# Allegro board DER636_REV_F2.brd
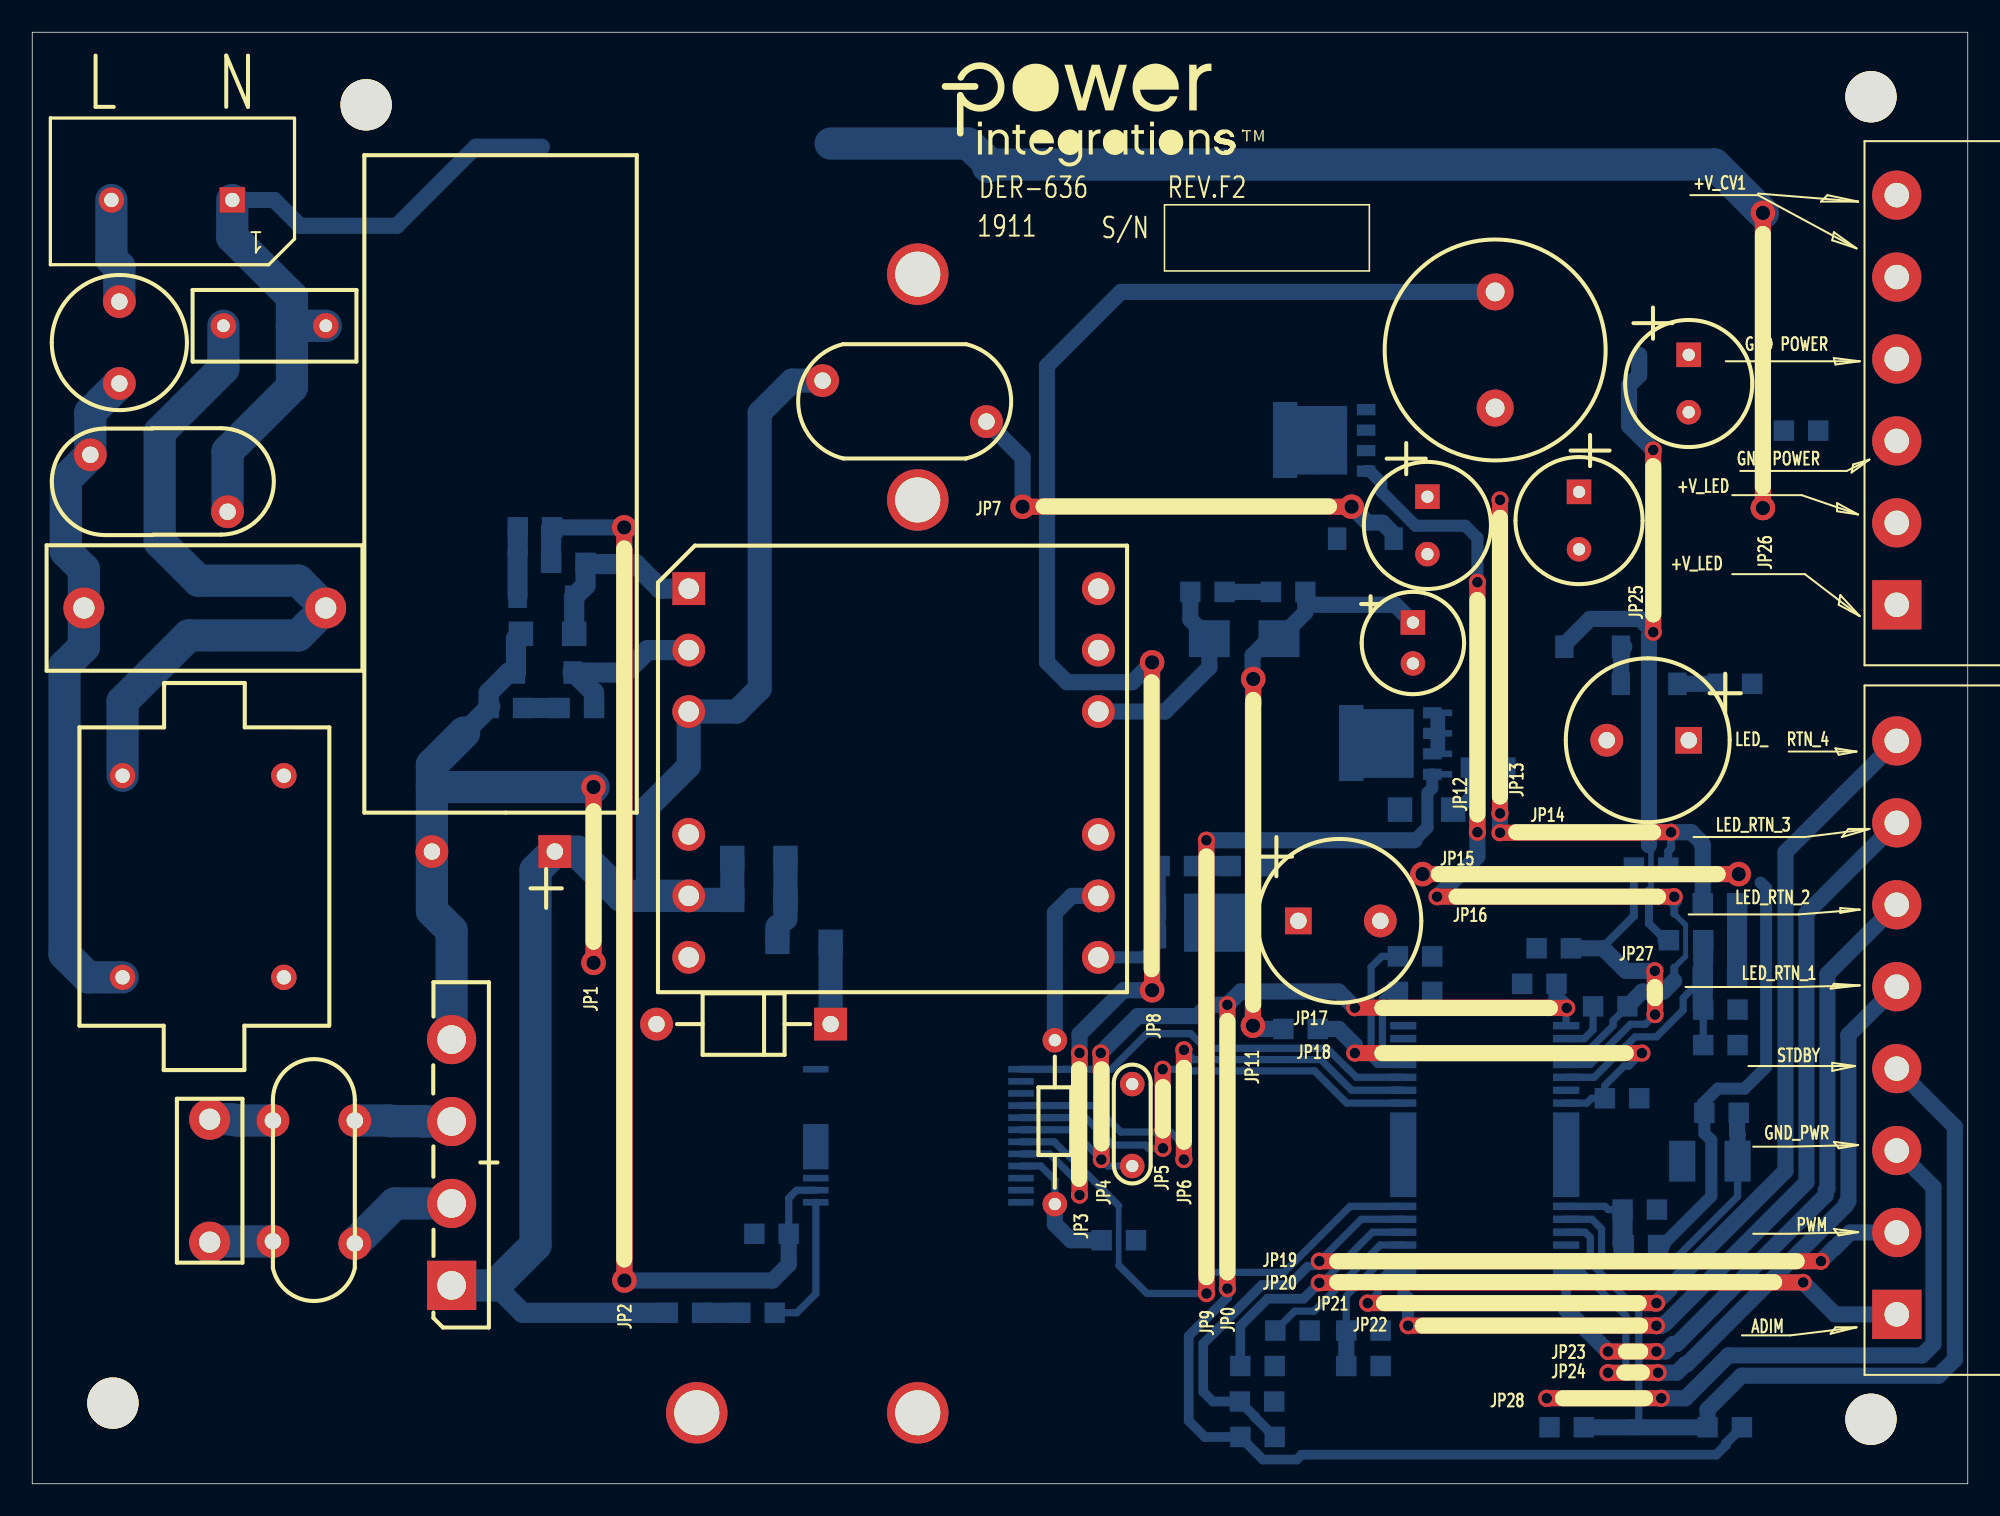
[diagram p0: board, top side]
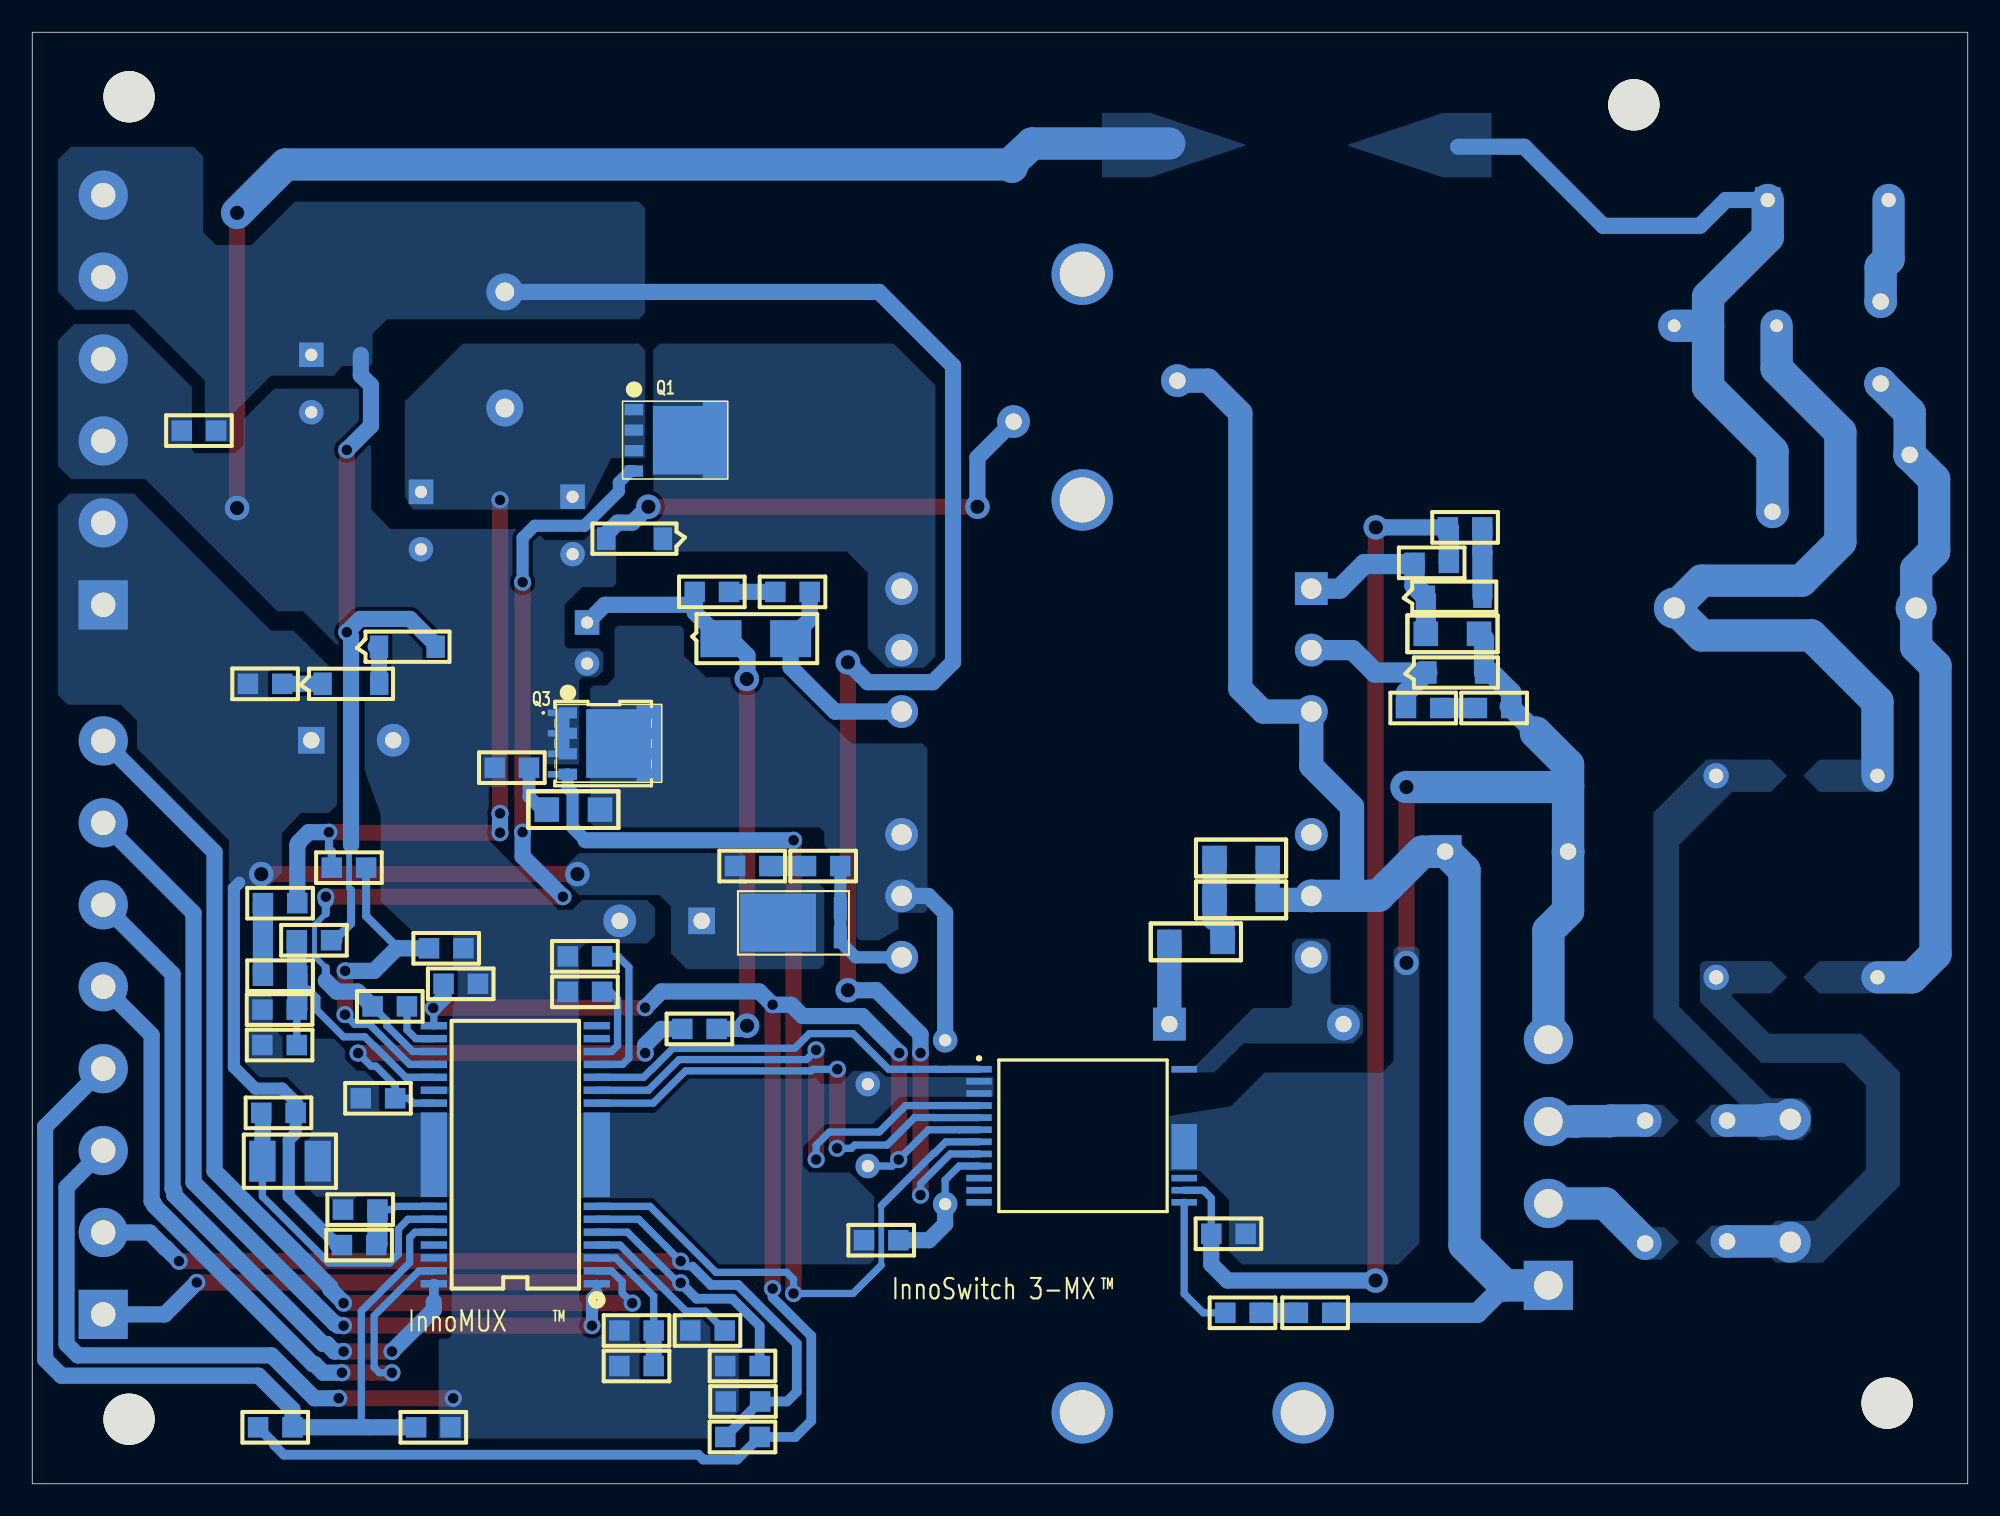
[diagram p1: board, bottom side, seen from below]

Outline 120 x 90 mm; copper layers: TOP, LAYER2, LAYER3, LAYER4, LAYER5, LAYER6, LAYER7, LAYER8, LAYER9, BOTTOM. Coordinates in mm from the lower left corner of the outline.
Outline path: 0,90 0,0 120,0 120,90 0,90

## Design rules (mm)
constraint set DEFAULT: min track width 0.1

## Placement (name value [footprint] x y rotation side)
BR1  GBU4J-BP  [PIDAXBRIDGEGBU8]  26 12.3 90 top
C1  33 nF  [PI_NP_CAP400X160LS300D040]  11 14.98 90 top
C2  220 nF  [PI_NP_710X315LS590D040]  3.2 54.3 0 top
C3  100 uF  [PIPOLCAPCLYD630LS300040]  32.4 39.2 180 top
C4  1000 uF  [PIPOLCAPCLYD320LS140030]  86.5 61.2 270 top
C5  1000  uF  [PIPOLCAPCLYD320LS140030]  102.7 70 270 top
C6  1 uF  [PISMC0805]  108.6 65.3 0 bottom
C7  1000 uF  [PIPOLCAPCLYD320LS140030]  95.9 61.5 270 top
C8  100 uF  [PIPOLCAPCYLD250LS100030]  85.6 53.4 270 top
C9  470 nF  [PISMC0805]  105.7 31.5 180 bottom
C10  100 pf  [PISMC0805]  76.8 55.3 0 bottom
C11  3.3 nF  [PINPYCAPRAD540X290LS400040]  49 68.4 0 top
C12  100 pf  [PISMC0805]  74.3 38.3 0 bottom
C13  1  nF  [PISMC1206]  43.4 38.8 0 bottom
C14  56 uF  [PIPOLCAPCYLD400LS200040]  78.5 34.9 0 top
C15  56 uF  [PIPOLCAPCYLD400LS200040]  102.7 46.1 180 top
C16  1 nF  [PISMC0805]  89.2 44.4 0 bottom
C17  100 nF  [PISMC0805]  95.4 33.2 180 bottom
C18  100 nF  [PISMC1210]  102.3 20 0 bottom
C19  100 nF  [PISMC0805]  97.5 23.9 0 bottom
C20  220 nF  [PISMC0805]  98.9 29.6 180 bottom
C21  100 nF  [PISMC0805]  79.2 9.5 180 bottom
C22  2.2 nF  [PISMC0805]  66.3 15.1 0 bottom
C23  2.2 uF  [PINPCAPRAD200X100200030]  68.2 19.7 90 top
C24  2.2 uF  [PISMC0805]  94.5 31 180 bottom
C28  100 pf  [PISMC0805]  28.3 48.1 0 bottom
C30  22 uF  [PISMC1206]  33.6 52.7 180 bottom
C31  4.7 uF  [PISMC0805]  46.9 15.5 180 bottom
CON2  TERMINAL BLOCK  [PI_TRMBLK_5P08_8PIN_H]  115.6 10.5 0 top
CON3  TERMINAL BLOCK  [PI_TRMBLK_5P08_6PIN_H]  115.6 54.5 0 top
D1  ES1C-13-F  [PISMDO214AC12]  77.3 52.4 180 bottom
D2  MMSZ5252BT1G  [PI_SM_SOD-123_12]  80.9 58.6 0 bottom
D3  PDU620-13  [PISMDPOWERDI5]  69.9 33.9 90 bottom
D4  BYV26C  [PIDV200X150X040SOD57]  49.5 28.5 180 top
D5  BAT46W-TP  [PI_SM_SOD-123_12]  33.5 50.3 180 bottom
D6  MMSZ5246B-7-F  [PI_SM_SOD-123_12]  33.6 55 180 bottom
F1  2 A  [PI_TR5_SUBMIN_FUSE]  5.4 73.3 270 top
J1  CON2  [PI_HDR_2PIN_PHOENIX_LS295]  12.4 79.6 180 top
L1  15 mH  [PIIND4P944X650LS492X394060]  15.6 43.9 270 top
L2  200 uH  [PI_COIL_2]  20 14.9 90 top
L3  10 uH  [PI_CHOKE_H625XD539LS290D046]  90.7 66.7 90 top
MTG_HOLE1  M 3  [PIMTGHOLEM3]  20.7 85.5 0 top
MTG_HOLE2  M 3  [PIMTGHOLEM3]  114 86 0 top
MTG_HOLE3  M 3  [PIMTGHOLEM3]  114 4 0 top
MTG_HOLE4  M 3  [PIMTGHOLEM3]  5 5 0 top
MTG_HOLE5  M 3  [PIMTGHOLEM3]  41.2 4.4 0 top
MTG_HOLE6  M 3  [PIMTGHOLEM3]  54.9 4.4 0 top
MTG_HOLE7  M 3  [PIMTGHOLEM3]  54.9 61 0 top
MTG_HOLE8  M 3  [PIMTGHOLEM3]  54.9 75 0 top
NOREF  -  []  120 0 90 top
NOREF#2  -  []  56.4 88.1 0 top
NOREF#3  -  []  0 90 0 top
Q1  SI4154DY-T1-GE3  [PI_SM_SOT669]  82.7 66.6 270 bottom
Q2  SQJA62EP-T1_GE3  [PISMPQFN5X6B]  87.4 47.8 270 bottom
Q3  SI4154DY-T1-GE3  [PI_SM_SOT669]  86.8 47.8 270 bottom
R1  10  [PIRAD400X175LS250031]  18.2 71.8 180 top
R2  10 k  [PISMR0805]  105.7 36 180 bottom
R3  10  [PISMR0805]  99.3 38.2 0 bottom
R4  10  [PISMR0805]  71.8 55.3 0 bottom
R5  10 k  [PISMR0805]  103.6 33.7 180 bottom
R6  100  [PISMR0805]  104.5 49.6 0 bottom
R7  390 k  [PISMR1206]  43.4 36.2 0 bottom
R8  10  [PISMR0805]  69.9 38.3 0 bottom
R9  10  [PISMR0805]  105.8 23 180 bottom
R10  10  [PISMR0805]  79.7 28.2 180 bottom
R11  121 k  [PISMR0805]  100.8 14.8 180 bottom
R12  3.30 k  [PISMR0805]  98.6 17 0 bottom
R13  10  [PISMR1206]  46.2 33.6 0 bottom
R14  18  [PISMR1206]  84.8 41.8 0 bottom
R15  68 k  [PISMR0805]  103.6 27.2 0 bottom
R16  3.30 k  [PISMR0805]  103.6 29.4 0 bottom
R17  47  [PI18WRESD080LS400D030]  63.4 27.5 270 top
R18  10 k  [PISMR0805]  83.6 9.5 180 bottom
R19  39 k  [PISMR0805]  86.8 30.5 180 bottom
R20  10  [PISMR0805]  32.7 48.1 0 bottom
R21  47.0  [PISMR0805]  30.1 59.3 0 bottom
R22  10 k  [PISMR0805]  34.3 57.1 180 bottom
R23  100 k  [PISMR0805]  74.9 7.3 0 bottom
R24  100 k  [PISMR0805]  96.2 3.5 180 bottom
R25  100 k  [PISMR0805]  77 5.1 180 bottom
R26  1.00 k  [PISMR0805]  106 3.5 180 bottom
R27  1.00 k  [PISMR0805]  74.9 2.9 0 bottom
R28  2 M  [PISMR0805]  39.4 10.6 0 bottom
R29  2 M  [PISMR0805]  43.9 10.6 0 bottom
R30  22 k  [PISMR0805]  86.8 32.7 180 bottom
R34  39 k  [PISMR0805]  83.6 7.3 180 bottom
T1  PQ26/20  [PI_BOBBIN_BPQ26_20_12P]  40.7 55.5 0 top
U1  MINNO (B)  [PI_SM_HSOP28_ALT]  85 12.4 90 bottom
U2  MINNO (A)  [PI_IC_INSOP_24D_IPC]  61.3 25.7 180 bottom
VDR1  275 Vac  [PIDISC500X225LS335X140040]  3.6 63.8 0 top
VR1  MMSZ5250B-7-F  [PI_SM_SOD-123_12]  98.5 51.9 180 bottom
VR2  MMSZ5245B-7-F  [PI_SM_SOD-123_12]  102 49.6 180 bottom

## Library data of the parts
BR1 = DISCRETE BRIDGE_+~~-
C1 C2 C6 C9 C10 C12 C13 C17-C24 C28 C30 C31 = CAP NP
C3 = CAP POL: alternate symbols: (pipolcapd630ls3000401600lhoriz)
C4 C7 = CAP POL
C5 = CAP POL: alternate symbols: (pipolcapclyd320ls140d30h750)
C8 = CAP POL: alternate symbols: (pipolcapcyld250ls100030h)
C11 = CAP NP: alternate symbols: (pinpycaprad540x290ls400040h)
C14 C15 = CAP POL: alternate symbols: (pipolcapcyld10ls514HD040H)
C16 = CAP NP: alternate symbols: (pismc0805_1)
CON2 = CON8
CON3 = CON6
D1 = DIODE
D2 D5 D6 VR1 VR2 = DIODE_ZENER
D3 = DIODE_PD5
D4 = DIODE: alternate symbols: (pidax425x150040sod57)
F1 = FUSE
J1 = CON2
L1 = INDUCTOR_4P_revD
L2 = TORRID 4P_14_23
L3 = INDUCTOR
MTG_HOLE1-MTG_HOLE8 = MTG_HOLE_M3
Q1 Q3 = FET_N_SGD_123_4_5: alternate symbols: (pismso8)
Q2 = FET_N_SGD_123_4_5678
R1 = THERMISTOR: alternate symbols: (pirad400x175ls250040_h)
R2-R16 R18-R30 R34 = R
R17 = R: alternate symbols: (pi18wresd080ls300d030,pi18wresd080ls400d030)
T1 = BPQ26/20_12P/GENERIC
U1 = MINNO_Master_HSOP
U2 = MinnoPriSec: alternate symbols: (pi_ic_insop_24d)
VDR1 = VARISTOR

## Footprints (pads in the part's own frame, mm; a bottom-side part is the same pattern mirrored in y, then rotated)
PI18WRESD080LS400D030
  round 1.52 hole 0.76: 1(0,0) 2(10.16,0)
PI_BOBBIN_BPQ26_20_12P
  rect 2.032x2.032 hole 1.27: 1(0,0)
  round 2.032 hole 1.27: 2(0,-3.81) 3(0,-7.62) 4(0,-15.24) 5(0,-19.05) 6(0,-22.86) 7(25.4,-22.86) 8(25.4,-19.05) 9(25.4,-15.24) 10(25.4,-7.62) 11(25.4,-3.81) 12(25.4,0)
PI_CHOKE_H625XD539LS290D046
  round 2.286 hole 1.168: 1(0,0) 2(7.2,0)
PI_COIL_2
  round 2.03 hole 1.02: 1(0.127,5.08) 2(7.62,5.08) 3(7.62,0) 4(0,0)
PI_HDR_2PIN_PHOENIX_LS295
  rect 1.575x1.575 hole 0.889: 1(0,0)
  round 1.575 hole 0.889: 2(7.493,0)
PI_IC_INSOP_24D_IPC
  rect 1.58x0.41 smd: 1(0,0) 2(0,-0.75) 3(0,-1.5) 4(0,-2.25) 5(0,-3) 6(0,-3.75) 7(0,-4.5) 8(0,-5.25) 9(0,-6) 10(0,-6.75) 11(0,-7.5) 12(0,-8.25) 13(12.72,-8.25) 14(12.72,-7.5) 15(12.72,-6.75) 24(12.72,0)
  rect 1.58x2.81 smd: 16(12.72,-4.8)
PI_NP_710X315LS590D040
  round 2.54 hole 1.32: 1(0,0) 2(14.99,0)
PI_NP_CAP400X160LS300D040
  round 2.54 hole 1.32: 1(0,0) 2(7.62,0)
PI_SM_HSOP28_ALT
  rect 0.46x1.63 smd: 1(0,0) 2(0.8,0) 3(1.6,0) 4(2.4,0) 5(3.2,0) 6(4,0) 7(4.8,0) 8(11.2,0) 9(12,0) 10(12.8,0) 11(13.6,0) 12(14.4,0) 13(15.2,0) 14(16,0) 15(16,10.1) 16(15.2,10.1) 17(14.4,10.1) 18(13.6,10.1) 19(12.8,10.1) 20(12,10.1) 21(11.2,10.1) 22(4.8,10.1) 23(4,10.1) 24(3.2,10.1) 25(2.4,10.1) 26(1.6,10.1) 27(0.8,10.1) 28(0,10.1)
  rect 5.25x1.63 smd: GND1(8,0) GND2(8,10.1)
PI_SM_SOD-123_12
  rect 1.14x1.4 smd: 1(0,0) 2(3.51,0)
PI_SM_SOT669
  rect 0.7x1.15 smd: 1(0,0) 2(1.27,0) 3(2.54,0) 4(3.81,0)
  rect 4.7x1.5 smd: 5(1.875,5.025)
PI_TR5_SUBMIN_FUSE
  round 2.03 hole 1.02: 1(0,0) 2(5.08,0)
PI_TRMBLK_5P08_6PIN_H
  rect 3.05x3.05 hole 1.52: 1(0,0)
  round 3.05 hole 1.52: 2(0,5.08) 3(0,10.16) 4(0,15.24) 5(0,20.32) 6(0,25.4)
PI_TRMBLK_5P08_8PIN_H
  rect 3.05x3.05 hole 1.52: 1(0,0)
  round 3.05 hole 1.52: 2(0,5.08) 3(0,10.16) 4(0,15.24) 5(0,20.32) 6(0,25.4) 7(0,30.48) 8(0,35.56)
PIDAXBRIDGEGBU8
  rect 3.048x3.048 hole 1.778: 1(0,0)
  round 3.048 hole 1.778: 2(5.08,0) 3(10.16,0) 4(15.24,0)
PIDISC500X225LS335X140040
  round 2.03 hole 1.02: 1(0,0) 2(8.509,-3.531)
PIDV200X150X040SOD57
  rect 2.032x2.032 hole 1.016: 1(0,0)
  round 2.032 hole 1.016: 2(10.795,0)
PIIND4P944X650LS492X394060
  round 1.575 hole 0.889: 1(12.5,-10) 2(12.5,0) 3(0,0) 4(0,-10)
PIMTGHOLEM3
  round 3.81 hole 2.794: 1(0,0)
PINPCAPRAD200X100200030
  round 1.52 hole 0.76: 1(0,0) 2(5.08,0)
PINPYCAPRAD540X290LS400040
  round 2.03 hole 1.02: 1(0,0) 2(10.16,-2.54)
PIPOLCAPCLYD320LS140030
  rect 1.52x1.52 hole 0.76: 1(0,0)
  round 1.52 hole 0.76: 2(3.56,0)
PIPOLCAPCLYD630LS300040
  rect 2.03x2.03 hole 1.02: 1(0,0)
  round 2.03 hole 1.02: 2(7.62,0)
PIPOLCAPCYLD250LS100030
  rect 1.52x1.52 hole 0.76: 1(0,0)
  round 1.52 hole 0.76: 2(2.54,0)
PIPOLCAPCYLD400LS200040
  rect 1.65x1.65 hole 1.02: 1(0,0)
  round 2.03 hole 1.02: 2(5.08,0)
PIRAD400X175LS250031
  round 1.58 hole 0.79: 1(0,0) 2(6.35,0)
PISMC0805
  rect 1.27x1.27 smd: 1(0,0) 2(2.13,0)
PISMC1206
  rect 1.52x1.52 smd: 1(0,0) 2(3.3,0)
PISMC1210
  rect 1.626x2.54 smd: 1(0,0) 2(3.429,0)
PISMDO214AC12
  rect 2.54x2.29 smd: 1(0,0) 2(4.32,0)
PISMDPOWERDI5
  rect 1.397x0.813 smd: 1(0,0) 3(1.778,0)
  rect 3.607x4.699 smd: 2(0.889,3.861)
PISMPQFN5X6B
  rect 0.406x1.27 smd: 1(0,0) 2(1.27,0) 3(2.54,0) 4(3.81,0)
  rect 0.406x1.219 smd: 5(3.81,5.588) 6(2.54,5.588) 7(1.27,5.588) 8(0,5.588)
PISMR0805
  rect 1.27x1.27 smd: 1(0,0) 2(2.13,0)
PISMR1206
  rect 1.52x1.52 smd: 1(0,0) 2(3.3,0)

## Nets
GND POWER: C4.2 C5.2 C6.2 C7.2 C8.2 C11.2 C14.2 C15.2 C16.2 C17.2 C18.1 C19.2 C21.1 C22.2 C23.2 C24.2 CON2.3 CON3.3 CON3.4 D2.2 Q2.1 Q2.2 Q2.3(S3) Q3.1 Q3.2 Q3.3(S3) R12.2 R15.2 R16.2 R18.1 R19.1 R23.2 R24.2 R25.1 R30.1 R34.1 U1.20 U1.GND1 U1.GND2 U2.2 U2.3
VIN_DC_TX: BR1.1 C3.1 C11.1 C13.1 R7.1 R28.1 T1.3 T1.5
+V_CV1: C5.1 C6.1 CON3.5 CON3.6 L3.2 R5.2 U2.8(VOUT) VR1.2
+V_CV1_PRE: C4.1 C7.1 L3.1 Q1.1 Q1.2 Q1.3(S3) R2.2 R3.2
+V_LED: C12.2 C14.1 C15.1 CON3.1 CON3.2 D3.2(C) R6.2 R9.2 R11.1
ADIM: CON2.1 R23.1 U1.5
BIAS_1_TX: C30.1 D6.1 R22.1 T1.1
BIAS_2_TX: D5.1 R20.2 T1.2
BP5V: C23.1 C24.1 R26.1 R27.1 U1.15 U2.6
CV1_TX: D2.1 Q1.5 T1.11 T1.12
D1_TX: D4.2 T1.6 U2.24
GDR1: C20.1 Q1.4 U1.17
LED_RTN3: CON2.7 U1.1
LED_RTN4: CON2.8 U1.2
LED_RTN_1: CON2.5 U1.27
LED_RTN_2: CON2.6 U1.28
LED_TX: D3.1 D3.3 R8.1 T1.7
LINE: F1.1 J1.2
NEUTRAL: J1.1 R1.1 VDR1.2
PWM: CON2.2 R25.2 R27.2 U1.6
SR_D: Q2.5 Q2.6 Q2.7 Q2.8 Q3.5 R14.1 R17.1 T1.8 T1.9
SR_GDR: Q2.4 Q3.4 U1.7 U2.7
STDBY: CON2.4 R24.1 R26.2 U1.24
N264690: C2.1 F1.2 L1.1 VDR1.1
N264850: C1.1 L1.2 L2.1
N264859: C1.2 L1.3 L2.2
N264880: BR1.2 L2.4
N265348: C13.2 R7.2 R13.1
N265875: C31.1 R21.2 R22.2 U2.14
N265882: D6.2 R21.1
N266083: BR1.4 C3.2 C28.1 C30.2 C31.2 D5.2 U2.16
N266812: R29.2 U2.13
N268528: U1.8 U2.5
N268540: U1.9 U2.4
N268853: C12.1 R8.2
N269394: R11.2 R12.1 U1.22
N270162: C9.2 R5.1 R15.1 R16.1 U1.19
N270954: C21.2 U1.4
N271382: R19.2 U1.12
N276717: C20.2 U1.16
N282191: D1.2 R4.1 T1.10
N282590: C22.1 R17.2 U2.9
N283932: C8.1 C10.2 D1.1 R10.2
N291571: U1.10 U2.1
N311390: R28.2 R29.1
N348677: D4.1 R13.2
N374143: C16.1 R14.2
N467521: C2.2 L1.4 R1.2
N471745: C19.1 R10.1 U1.21
N472207: C17.1 R3.1 U1.18
N535301: C18.2 R9.1 U1.23(VLED)
N551504: BR1.3(AC2) L2.3
N563936: VR1.1 VR2.2
N600270: R30.2 U1.11
N606979: R18.2 R34.2 U1.3
N615359: R6.1 VR2.1
N2821191: C10.1 R4.2
N3812470: C9.1 R2.1
N4964340: C28.2 R20.1

Pads without a net: MTG_HOLE1 1; MTG_HOLE2 1; MTG_HOLE3 1; MTG_HOLE4 1; MTG_HOLE5 1; MTG_HOLE6 1; MTG_HOLE7 1; MTG_HOLE8 1; T1 4; U1 13 14 25 26; U2 10 11 12 15

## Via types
v1: diameter 1.067, hole 0.66, TOP to BOTTOM, 42 vias
v2: diameter 1.524, hole 0.889, TOP to BOTTOM, 14 vias

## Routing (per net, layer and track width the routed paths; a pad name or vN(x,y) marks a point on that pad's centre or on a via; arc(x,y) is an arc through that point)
GND POWER: length 146.6
  TOP w1: v2(107.3,78.8) v2(107.3,60.5) ; v2(81.8,60.58) v2(61.4,60.58) ; v1(93.9,5.3) v1(101,5.3)
  BOTTOM w1: C11.2 61.4,63.62 v2(61.4,60.58) ; v2(81.8,60.58) 82.78,59.59 83.71,59.59 84.41,58.89 D2.2 ; v1(101,5.3) 102.5,5.3 105.16,7.96 117.17,7.96 117.87,8.66 117.87,18.39 CON2.3
  BOTTOM w2: 59.41,81.8 104.3,81.8 v2(107.3,78.8) ; 59.41,81.8 58.01,83.1 49.5,83.1 ; 59.41,81.8 59.26,81.65
VIN_DC_TX: length 97.6
  BOTTOM w0.1: 43.48,37 43.48,36.28 R7.1
  BOTTOM w1.25: 28.7,12.3 30.4,10.6 R28.1
  BOTTOM w1.5: C13.1 R7.1 40.95,36.2 T1.5 ; 38.18,36.45 38.18,41.97 40.7,44.5 T1.3 43.68,47.88 45.1,49.3 45.1,66.39 47.11,68.4 C11.1
  BOTTOM w2: 32.36,39.19 33.81,39.19 36.55,36.45 T1.5 ; 32.36,39.19 31.2,38.03 31.2,14.8 28.7,12.3 BR1.1 ; 32.36,39.19 C3.1
+V_CV1: length 141.3
  TOP w1: v1(64.93,17.9) v1(64.93,26.71) ; v2(69.43,30.6) 69.43,30.9 69.43,30.9 v2(69.43,50.93) ; v1(100.5,52.8) v1(100.5,64.1)
  BOTTOM w0.35: 100.24,39.58 100.24,39.36 100.36,39.24 100.36,36.94 100.24,36.82
  BOTTOM w0.45: U2.8 61.7,20.45 63.08,20.45 64.93,18.6 v1(64.93,17.9)
  BOTTOM w0.5: 100.24,36.82 100.24,34.74 101.27,33.7
  BOTTOM w1: v2(69.43,50.93) 68.2,49.7 64.15,49.7 62.91,50.94 62.91,69.31 67.5,73.9 L3.2 ; v1(100.5,64.1) 99,65.6 99,68.1 99.63,68.73 99.63,70 ; VR1.2 94.99,52.03 96.58,53.62 99.68,53.62 v1(100.5,52.8) 100.24,52.54 100.24,39.58 ; R5.2 101.27,33.7 ; v2(69.43,30.6) 67.66,30.6 64.93,27.87 v1(64.93,26.71)
+V_CV1_PRE: length 39.5
  TOP w1: v1(101.61,40.4) 100.44,40.4 100.41,40.37 v1(91,40.37) ; v1(91,41.56) v1(91,61)
  BOTTOM w0.5: v1(101.61,40.4) 101.61,39.39 101.43,39.22 R3.2
  BOTTOM w1: v1(101.61,40.4) 102.77,40.4 102.77,40.4 102.87,40.4 103.5,39.76 103.5,39.67 103.57,39.6 R2.2 ; v1(91,41.56) v1(91,40.37)
+V_LED: length 46.6
  TOP w1: v2(105.8,37.8) v2(86.2,37.8)
  BOTTOM w0.75: 107.16,37.27 107.5,36.93 107.5,25.84 106.16,24.5 104.5,24.5 103.57,23.57 103.57,23.1 ; 101.07,14.8 104.1,17.83 104.1,21.31 103.67,21.74 R9.2
  BOTTOM w1: 103.57,23.1 R9.2 ; R11.1 101.07,14.8
ADIM: length 51.6
  TOP w1: v1(79.8,12.46) 82.01,12.46 82.03,12.48 106.93,12.48 106.94,12.48 v1(109.8,12.48)
  BOTTOM w0.45: v1(79.8,12.46) 79.96,12.46 83.1,15.6 U1.5
  BOTTOM w0.6: v1(79.8,12.46) 78.82,11.47 76.59,11.47 74.9,9.78 R23.1
  BOTTOM w1: CON2.1 111.78,10.5 v1(109.8,12.48)
BIAS_1_TX: length 11.7
  BOTTOM w1.25: 34.3,57.03 R22.1 ; 34.3,57.03 34.3,55.7 D6.1 C30.1 ; 34.3,57.03 37.4,57.03 38.93,55.5 T1.1
BIAS_2_TX: length 10.5
  BOTTOM w1.25: T1.2 38.15,51.69 36.75,50.3 33.58,50.3 ; 33.58,50.3 34.83,49.05 R20.2 ; 33.58,50.3 D5.1
BP5V: length 111.2
  TOP w1: v1(82,29.52) 93.96,29.52 93.97,29.5 v1(95.14,29.5) ; v1(74.1,12.1) v1(74.1,29.7) ; v1(66.28,20.1) 66.28,21.26 66.26,21.28 66.26,25.53 66.25,25.54 v1(66.25,26.71)
  BOTTOM w0.45: v1(66.28,20.1) 66.28,20.1 ; 66.28,20.1 66.69,19.7 C23.1 ; 66.28,20.1 64.44,21.95 62.53,21.95 U2.6 ; U1.15 95.1,29.46 v1(95.14,29.5)
  BOTTOM w0.6: v1(74.1,12.1) 74.1,11.56 71.7,9.16 71.7,3.9 72.7,2.9 R27.1 76.3,1.5 78.4,1.5 78.7,1.8 104.4,1.8 105,2.4 105,2.5 R26.1
  BOTTOM w1: v1(82,29.52) 80.99,30.52 74.92,30.52 v1(74.1,29.7) 72.94,29.7 72.24,29 68.54,29 v1(66.25,26.71) ; v1(95.14,29.5) 94.5,30.14 C24.1
CV1_TX: length 0.1
  BOTTOM w1: T1.11 66.19,51.6
GDR1: length 61.4
  TOP w1: v1(89.6,40.4) 89.6,42.8 89.6,42.8 89.6,54.73 89.6,54.74 v1(89.6,55.9) ; v1(87.1,36.4) v1(101.8,36.4)
  BOTTOM w0.3: 102.5,32.7 102.5,34.64
  BOTTOM w0.35: 102.5,34.64 101.8,35.35 ; 101.8,32 102.5,32.7
  BOTTOM w0.45: U1.17 96.41,26.8 98.01,28.4 98.01,28.71 C20.1
  BOTTOM w0.5: 101.8,35.35 101.8,36.2 ; 101.8,31.19 101.8,32
  BOTTOM w0.75: v1(89.6,55.9) 89.6,58.65 88.85,59.4 85.76,59.4 83.63,61.53 83.63,62.08 82.93,62.79 Q1.4
  BOTTOM w1: 101.8,36.2 v1(101.8,36.4) ; v1(89.6,40.4) 89.6,38.9 v1(87.1,36.4) ; 101.8,31.19 101.13,30.52 99.82,30.52 C20.1
LED_RTN3: length 55.7
  TOP w1: v1(85.3,9.8) 99.53,9.8 99.54,9.8 v1(100.7,9.8)
  BOTTOM w0.5: U1.1 85,11.81
  BOTTOM w0.75: v1(85.3,9.8) 85.3,10.69 85.3,11.51 85,11.81
  BOTTOM w1: v1(100.7,9.8) 101.03,9.8 101.15,9.92 101.23,9.92 110,18.69 110,35.38 CON2.7
LED_RTN4: length 62.4
  TOP w1: v1(82.8,11.2) 83.96,11.2 83.97,11.2 100.53,11.2 100.54,11.2 v1(100.7,11.2)
  BOTTOM w0.45: U1.2 84.08,13.2 83.43,12.55 83.43,11.83 v1(82.8,11.2)
  BOTTOM w1: CON2.8 108.7,39.16 108.7,19.4 102.88,13.58 102.88,13.56 101.52,12.2 101.52,12.06 100.73,11.27 100.73,11.23 v1(100.7,11.2)
LED_RTN_1: length 43.2
  TOP w1: v1(97.7,6.88) 98.86,6.88 98.87,6.89 v1(100.8,6.89)
  BOTTOM w0.45: v1(97.7,6.88) 98.48,6.88 98.8,7.2 98.8,10.42 96.02,13.2 U1.27
  BOTTOM w1: v1(100.8,6.89) 101.96,6.89 102.49,7.42 102.6,7.42 112.45,17.26 112.45,17.37 112.6,17.52 112.6,27.82 CON2.5
LED_RTN_2: length 42.6
  TOP w1: v1(97.7,8.2) v1(100.7,8.2)
  BOTTOM w0.6: 95.1,11.3 U1.28
  BOTTOM w1: CON2.6 111.3,31.6 111.3,18.3 111.2,18.2 111.2,17.9 101.97,8.67 101.73,8.67 101.26,8.2 v1(100.7,8.2) ; v1(97.7,8.2) 95.1,10.8 95.1,11.3
LED_TX: length 8.9
  BOTTOM w0.75: T1.7 68.93,32.64 69.9,33.61 D3.1 D3.3 R8.1
LINE: length 6.5
  BOTTOM w2: J1.2 4.91,75.94 5.4,75.45 F1.1
NEUTRAL: length 46.5
  BOTTOM w1: J1.1 15,79.6 16.6,78 22.6,78 27.5,82.9 31.6,82.9
  BOTTOM w2: 16.1,71.8 16.1,68 12.11,64.01 VDR1.2 ; 16.1,71.8 R1.1 ; 16.1,71.8 16.1,73.6 12.4,77.3 J1.1
PWM: length 60.7
  TOP w1: v1(110.9,13.8) v1(79.8,13.8)
  BOTTOM w0.45: U1.6 82.4,16.4 v1(79.8,13.8) 79.47,13.47 79.07,13.47
  BOTTOM w0.6: 79.07,13.47 77.92,12.32 76.24,12.32 72.6,8.69 72.6,5.7 73.2,5.1 R25.2 75.81,4.16 75.81,4.12 R27.2
  BOTTOM w1: CON2.2 112.72,15.58 111.76,14.62 111.72,14.62 v1(110.9,13.8)
SR_D: length 11
  BOTTOM w1: T1.8 64.45,36.45 63.4,35.4 R17.1
SR_GDR: length 78.1
  TOP w1: v1(72.8,39.9) 72.8,13.08 72.8,13.08 v1(72.8,11.8)
  BOTTOM w0.35: 67.36,13.55 67.36,17.24
  BOTTOM w0.45: U2.7 63.36,21.2 64.07,20.49 64.11,20.49 67.36,17.24 ; U1.7 81.7,17.2 77.61,13.11 73.23,13.11 72.8,12.68 v1(72.8,11.8) 69.11,11.8 67.36,13.55
  BOTTOM w0.75: Q3.4 86.8,43.13 86.5,42.83 86.5,40.7
  BOTTOM w0.8: 86.5,40.7 85.7,39.9
  BOTTOM w1: 85.7,39.9 v1(72.8,39.9)
STDBY: length 59.7
  BOTTOM w0.45: U1.24 96.27,15.6 96.6,15.27 96.6,13.7 99.6,10.7 99.6,3.95 99.15,3.5
  BOTTOM w1: CON2.4 119.2,22.14 119.2,7.71 118.19,6.7 105.97,6.7 103.87,4.6 R26.2 R24.1
N264690: length 41.9
  BOTTOM w2: F1.2 3.6,66.42 VDR1.1 2.08,62.28 2.08,57.82 3.2,56.7 C2.1 3.2,51.9 2,50.7 2,32.85 3.45,31.4 L1.1
N264850: length 3.9
  BOTTOM w2: L2.1 11.23,15.03 11.18,14.98 C1.1
N264859: length 4
  BOTTOM w0.1: 12.51,22.54 12.45,22.6
  BOTTOM w2: 12.45,22.6 C1.2 ; 12.51,22.54 12.76,22.54 12.78,22.52 L2.2
N264880: length 7
  BOTTOM w2: BR1.2 22.48,17.38 L2.4
N265348: length 5.4
  BOTTOM w0.1: 46.2,34.54 46.7,35.04
  BOTTOM w1.5: R13.1 46.2,34.54 ; C13.2 R7.2 46.7,35.04
N265875: length 70
  TOP w1: v2(36.7,59.3) 36.7,57.81 36.72,57.79 v2(36.72,12.6)
  BOTTOM w0.45: C31.1 46.9,17.7 47.06,17.86 47.06,17.87 47.34,18.15 47.35,18.15 47.4,18.2 U2.14
  BOTTOM w1: v2(36.72,12.6) 45.9,12.6 46.9,13.6 C31.1 ; v2(36.7,59.3) R21.2
  BOTTOM w1.25: R21.2 32.17,59.24 R22.2
N265882: length 4.3
  BOTTOM w1.25: D6.2 30.09,57.72 30.1,57.73 R21.1
N266083: length 49.3
  TOP w1: v2(34.8,32.3) v2(34.8,43.2)
  BOTTOM w1.25: C28.1 26.78,46.58 ; C28.1 28.4,48.2 ; C28.1 28.3,49.05 29.55,50.3 D5.2 29.99,52.39 C30.2
  BOTTOM w2: 24.78,43.23 24.78,44.58 26.78,46.58 ; 24.78,43.23 C3.2 24.78,35.52 26,34.3 BR1.4 ; 24.78,43.23 24.81,43.2 v2(34.8,43.2)
N266812: length 8.7
  BOTTOM w0.45: R29.2 47.4,10.6 48.58,11.78 U2.13
N268528: length 30.3
  TOP w1: v1(70.1,20.8) 70.1,21.96 70.08,21.98 v1(70.08,25.7)
  BOTTOM w0.45: v1(70.1,20.8) 69.21,20.8 69.01,21 67,21 65.29,22.71 64.07,22.71 64.06,22.7 U2.5 ; U1.8 81.5,23.6 79.5,25.6 71.71,25.6 71.61,25.7 v1(70.08,25.7)
N268540: length 33.4
  TOP w1: v1(71.4,20.1) 71.4,24.54 v1(71.4,26.9)
  BOTTOM w0.45: U2.4 62.45,23.45 65.85,23.45 67.49,21.81 70.58,21.81 71.4,20.99 v1(71.4,20.1) ; U1.9 81.8,24.4 79.9,26.3 72,26.3 v1(71.4,26.9)
N268853: length 2.3
  BOTTOM w1.25: R8.2 C12.1
N269394: length 5.8
  BOTTOM w0.45: U1.22 97.51,17.2 97.71,17 R12.1
  BOTTOM w1.25: R11.2 98.6,14.88 R12.1
N270162: length 19.1
  BOTTOM w0.1: C9.2 103.57,32.32 103.6,32.35
  BOTTOM w0.45: U1.19 96.84,25.2 98.74,27.1 98.77,27.1 99.38,27.71 100.7,27.71 102.36,29.37 102.36,30.13 102.9,30.67 103.57,30.67 103.79,30.45 103.79,29.68 103.6,29.49 R16.1 R15.1
  BOTTOM w1.25: R5.1 103.6,32.35 ; C9.2 103.57,29.43 R16.1
N270954: length 10.1
  BOTTOM w0.45: U1.4 83.57,14.8 79.47,10.7 78.27,10.7 C21.2
N271382: length 5.5
  BOTTOM w0.45: U1.12 84.08,26.8 83.71,27.17 83.71,30.05 84.16,30.5 R19.2
N276717: length 3.3
  BOTTOM w0.45: C20.2 96.77,28.15 96.22,27.6 U1.16
N282191: length 13.2
  BOTTOM w1: T1.10 70.24,47.88 72.98,50.62 D1.2 71.8,53.58 R4.1
N282590: length 8.5
  BOTTOM w0.45: U2.9 62.53,19.7 63.4,18.83 R17.2
  BOTTOM w1: R17.2 63.4,16.1 64.4,15.1 C22.1
N283932: length 41.3
  TOP w1: v2(75.7,49.9) 75.7,48.37 75.68,48.35 v2(75.68,28.4)
  LAYER9 w0.1: 77.3,52.7 77.3,51.5 v2(75.7,49.9)
  BOTTOM w1: 78.93,54.67 79.1,54.5 84.5,54.5 C8.1 ; 78.93,54.67 78.93,54.03 D1.1 76.7,52.4 75.66,51.36 75.66,49.94 v2(75.7,49.9) ; 78.93,54.67 C10.2 ; R10.2 75.88,28.2 v2(75.68,28.4)
N291571: length 25.7
  BOTTOM w0.45: U1.10 82.1,25.2 81.6,25.7 81.58,25.7 80.28,27 72.73,27 71.82,27.91 69.11,27.91 66.9,25.7 65.9,25.7 63.96,25.7 63.95,25.69 63.12,25.69 63.11,25.7 U2.1
N311390: length 2.4
  BOTTOM w1.25: R28.2 R29.1
N348677: length 5.1
  BOTTOM w1.5: R13.2 D4.1
N374143: length 3.2
  BOTTOM w0.8: R14.2 88.4,41.8 89.2,42.6 C16.1
N467521: length 46.6
  BOTTOM w2: R1.2 11.85,69.15 7.9,65.2 7.9,58.4 10.3,56 16.49,56 C2.2 16.49,52.6 9.7,52.6 5.6,48.5 L1.4
N471745: length 27.5
  TOP w1: v1(82,26.7) 85.17,26.7 v1(99.8,26.7)
  BOTTOM w0.45: v1(99.8,26.7) 99,25.9 98.7,25.9 97.5,24.7 C19.1 96.68,23.9 96.38,23.6 U1.21
  BOTTOM w1: v1(82,26.7) 82,27.2 81,28.2 R10.1
N472207: length 21.1
  TOP w1: v1(100.61,29.09) 100.61,30.63 100.6,30.64 v1(100.6,31.8)
  BOTTOM w0.45: v1(100.61,29.09) 100.01,28.49 99.09,28.49 96.6,26 U1.18
  BOTTOM w0.5: 97.3,33.2 99.3,35.2 R3.1
  BOTTOM w1: v1(100.6,31.8) 98.8,31.8 97.4,33.2 C17.1
N535301: length 19.6
  BOTTOM w0.45: C18.2 105.73,17.81 101.91,13.99 101.91,13.97 101.63,13.69 97.84,13.69 97.3,14.23 97.3,15.8 96.7,16.4 U1.23
  BOTTOM w1: C18.2 105.73,21.7 105.7,21.73 105.7,22.9 R9.1
N551504: length 6
  BOTTOM w2: BR1.3 24.3,22.46 24.28,22.48 22.18,22.48 22.14,22.52 L2.3
N563936: length 2.5
  BOTTOM w1: VR2.2 98.5,49.61 VR1.1 98.71,51.9
N600270: length 9.7
  BOTTOM w0.45: R30.2 83.68,32.7 83.01,32.03 83.01,26.39 83.4,26 U1.11
N606979: length 8.8
  BOTTOM w0.45: R18.2 81.47,11.64 83.83,14 U1.3
  BOTTOM w1: R18.2 R34.2
N615359: length 2.5
  BOTTOM w1: VR2.1 R6.1
N2821191: length 2.9
  BOTTOM w1: R4.2 C10.1
N3812470: length 4.5
  BOTTOM w1.25: C9.1 R2.1
N4964340: length 2.3
  BOTTOM w1.25: R20.1 C28.2

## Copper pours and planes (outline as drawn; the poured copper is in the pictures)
GND POWER on BOTTOM (solid shape): 87.6,45.06 86.69,45.06 86.69,47.98 87.6,47.98
GND POWER on BOTTOM: outline of 130 points within 60.4,2.8 118.4,71.9
GND POWER on BOTTOM: 53.67,85 50.67,85 44.67,83 50.67,81 53.67,81
+V_CV1 on BOTTOM: 98.9,69.5 98.9,71.3 98,72.2 82.4,72.2 82,72.6 82,79.1 82.4,79.5 103.7,79.5 106.4,76.8 108.6,76.8 109.4,77.6 109.4,82.3 110,82.9 117.6,82.9 118.4,82.1 118.4,73.9 117.3,72.8 113.7,72.8 109.3,68.4 109.3,64.6 107.59,64.6 107.5,64.7 107.5,66.4 105.2,68.7 101.3,68.7 100.8,69.3 99.05,69.3
+V_CV1_PRE on BOTTOM: 82,70.3 82.4,70.7 93.3,70.7 96.9,67.1 96.9,61.2 96.4,60.4 85.7,60.4 84.1,63.6 82,63.6
+V_LED on BOTTOM: 101.09,50.19 101.11,42.09 101.6,41.6 103.33,41.6 104.53,40.33 104.53,37.87 105.3,37.1 107.5,37.1 107.8,37.4 107.8,39.9 113.5,45.6 113.5,47.3 114.5,48.3 117.8,48.3 118.4,48.9 118.4,60.7 117.7,61.4 113.7,61.4 105.2,52.9 103.8,52.9
+V_LED on BOTTOM: 70.9,36.9 70.9,32.2 71.2,31.9 79.4,31.9 80.4,32.9 80.4,35.8 81.1,36.5 86.1,36.5 86.9,37.3 86.9,38.3 86.1,39.1 76,39.1 75.8,38.9 75.8,37.3 75.7,37.2 71.2,37.2
CV1_TX on BOTTOM (solid shape): 78.42,67.07 78.42,66.83 81.53,66.83 81.53,62.58 78.42,62.58 78.42,62.38 76.92,62.38 76.92,67.08
CV1_TX on BOTTOM: 81.5,70.3 81.49,57.99 81.3,57.8 69.5,57.8 68.2,56.5 68.2,51.8 67,50.6 64.7,50.6 64,51.3 64,68.1 66.6,70.7 81.1,70.7
D1_TX on BOTTOM: 49.4,25.5 46.7,25.5 44.9,27.3 38.1,27.3 37.5,27.9 37.5,29.1 38.1,29.7 39.3,29.7 39.5,29.9 39.5,33.5 39.8,33.8 41.6,33.8 41.9,33.5 41.9,29.7 42.1,29.5 44.3,29.5 47.9,25.9 49.4,25.9
NEUTRAL on BOTTOM: 29.53,81 32.53,81 38.53,83 32.53,85 29.53,85
SR_D on BOTTOM (solid shape): 85.65,43.79 81.61,43.79 81.61,48 85.65,48
SR_D on BOTTOM (solid shape): 82.53,48.28 82.53,48.02 85.62,48.03 85.62,43.77 82.53,43.77 82.53,43.57 81.03,43.57 81.02,48.28
SR_D on BOTTOM: 78.2,50 73.4,50 69.2,45.9 64.8,45.9 64.5,45.6 64.5,35.63 64.68,35.4 66.2,35.4 66.3,35.3 66.3,34.38 67.52,33.7 68.7,33.7 68.9,33.9 68.9,39.1 69.1,39.3 70.6,39.3 70.9,39.6 70.9,40.4 71.2,40.7 85.1,40.7 85.4,41 85.4,49.3 85.2,49.5 84.4,49.5 83.9,50 83.9,53 83.7,53.2 79.8,53.2 79.6,53 79.6,51.33
N264690 on BOTTOM: 5.2,32.4 5.2,30.4 9.2,30.4 10.2,31.4 9.2,32.4
N264850 on BOTTOM: 16.2,30.4 16.2,32.4 12.2,32.4 11.2,31.4 12.2,30.4
N264850 on BOTTOM: 14.6,32.4 14.6,30.2 12.3,27.9 6.6,27.9 4.2,25.5 4.2,18.5 9,13.7 11.9,13.7 12.3,14.1 12.3,15.9 11.9,16.3 9.5,16.3 6.3,19.5 6.3,24.7 7.7,26.1 12.8,26.1 16.6,29.9 16.6,32.2 16.4,32.4
N264850 on BOTTOM: 11.9,16 11.9,14 15.9,14 16.9,15 15.9,16
N264859 on BOTTOM: 14.6,44.9 14.6,42.9 17.9,39.6 17.9,29.6 12.2,23.9 10.3,23.9 9.7,23.3 9.7,21.9 10.3,21.3 12.9,21.3 13.8,22.2 13.8,23.2 19.5,28.9 19.5,41.6 16.2,44.9
N264859 on BOTTOM: 16.2,42.9 16.2,44.9 12.2,44.9 11.2,43.9 12.2,42.9
N264859 on BOTTOM: 11.9,23.5 11.9,21.5 15.9,21.5 16.9,22.5 15.9,23.5
N264880 on BOTTOM: 20.3,13.9 22.3,15.9 18.8,15.9 17.9,15 19,13.9
N266083 on BOTTOM: 49.5,22.8 45.7,23.4 43.6,25.5 36.3,25.5 35.6,26.2 35.6,33.1 35.4,33.3 34.2,33.3 34,33.1 34,14.9 35.3,13.6 45,13.6 45.8,14.4 45.8,17.6 47.6,19.4 49.5,19.4
N467521 on BOTTOM: 5.2,44.9 5.2,42.9 9.2,42.9 10.2,43.9 9.2,44.9
N551504 on BOTTOM: 22.9,21.5 22.9,23.5 18.9,23.5 17.9,22.5 18.9,21.5

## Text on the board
Ref Des/Silkscreen Bottom: TM | InnoSwitch 3-MX | InnoMUX
User.Comments: 1 (ONE) CUTOUT HERE: | NOTES: UNLESS OTHERWISE SPECIFIED | 1.  THROUGH HOLES ARE NOT PLATED THROUGH. | 2.  MATERIAL: BASE MATERIAL LAMINATED EPOXY | 3.  SOLDER PLATE WILL BE RoHS COMPLIANT. | 4.  SOLDER MASK LPI (LIQUID PHOTO IMAGEABLE) BOTH SIDES. COLOR GREEN. | 5.  SILKSCREEN TOP/BOTTOM SIDE. COLOR WHITE.(MIN.WIDTH 0.005" MAX.WIDTH 0.010") | 6.  FINISH TO BE SMOBC. | 7.  LEAD FREE HASL (HOT AIR SOLDER LEVEL) OR RoHS COMPLIANT. | 8.  BOARD DIMENTION +/- 0.005" | 9.  DRILL TOLERANCE+/-0.003" | 10.  TRACE WIDTH UNDER 0.010" +/- 0.002" | 11.  TRACE SPACE +/- 0.003" | 12.  MATERIAL FR4 COPPER 2 OZ TOTAL BOARD THICKNESS 0.062" | 13. 1 LAYER BOARD (COPPER ON BOTTOM SIDE). | EXCEPTIONS WILL BE NOTED IN DRILL CHART "NOTE". | UL APPROVED MANUFACTURED SOURCE FOR FR4. | SOLDER MASK (REGISTRATION) -0/+0.003" | TRACE WIDTH OVER 0.011" +/- 0.005" | PLEASE DELETE THESE PINS (IF ANY).
Ref Des/Silkscreen Top: JP7 | JP19 | JP20 | JP17 | JP18 | JP21 | JP22 | JP15 | JP16 | JP28 | JP14 | JP23 | JP24 | JP27 | +V_LED | +V_CV1 | LED_RTN_3 | LED_ | LED_RTN_2 | GND POWER | LED_RTN_1 | ADIM | GND_PWR | STDBY | RTN_4 | PWM | JP1 | JP2 | JP3 | JP4 | JP8 | JP5 | JP6 | JP9 | JP0 | JP11 | JP12 | JP13 | JP25 | JP26 | 1911 | DER-636 | S/N | REV.F2 | L | N
User.12: FIGURE | FINISHED_SIZE | 26.0 | 29.921 | 31.098 | 35.0 | 40.0 | 40.161 | 45.98 | 50.0 | 51.969 | 59.839 | 70.0 | 110.0 | 125.0 | DRILL CHART: TOP to BOTTOM | ALL UNITS ARE IN MILS | TOOL_SIZE | 71 | - | PLATED | QTY | 42 | 12 | 2 | 14 | 6 | 16 | 4
